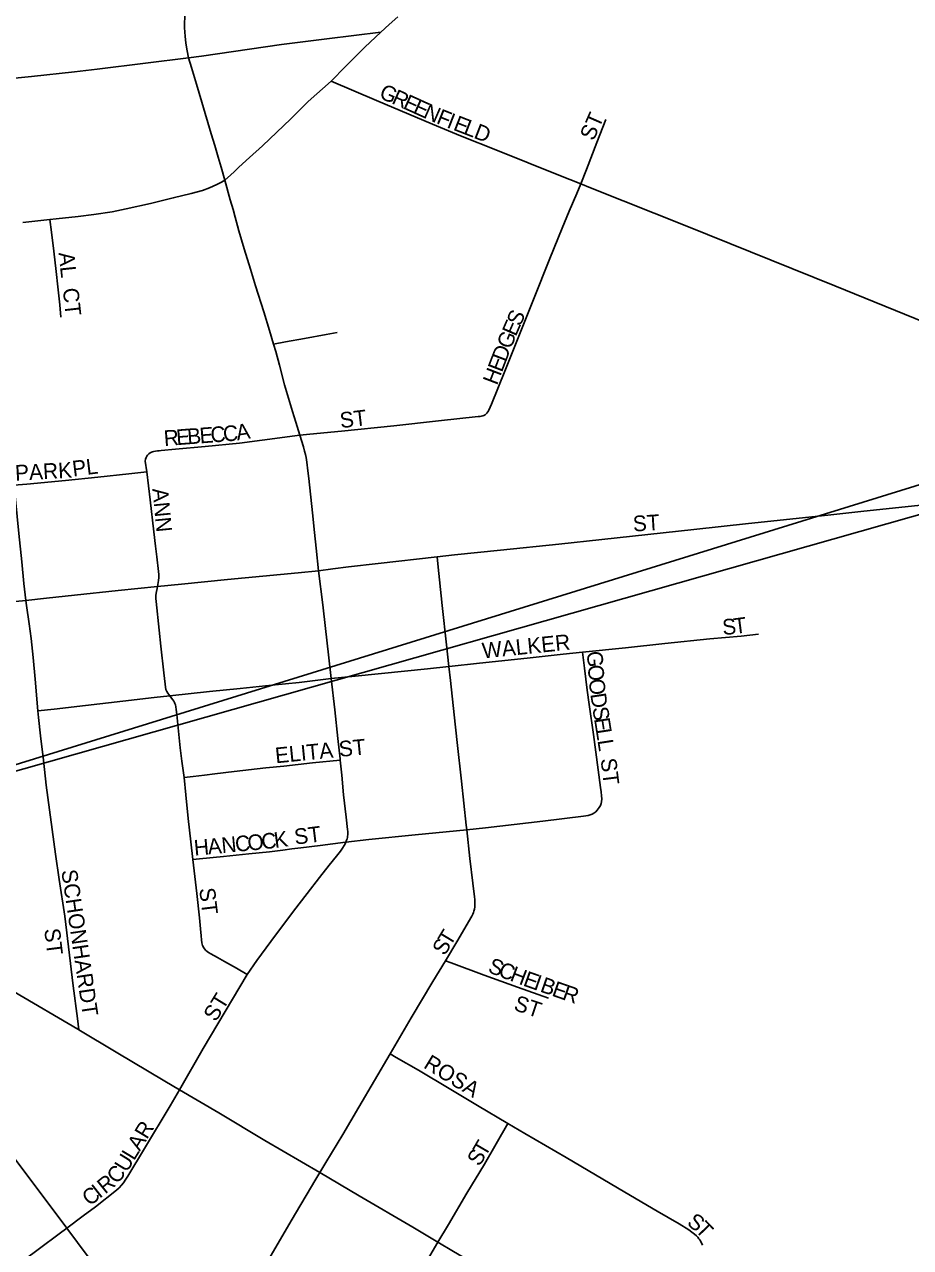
# Model space of a CAD drawing. Extents: x 1772825 to 1773716, y 1138558 to 1139032.
# Drawn here: x 1773356.3 to 1773367.01, y 1138861.97 to 1138876.75 of the extents above; entities that cross this region are included whole.
import ezdxf

# ---------------------------------------------------------------- set-up
doc = ezdxf.new("R2010")
doc.units = 0
for name, color, linetype in [('GM_X_City_Street', 7, 'Continuous'), ('GM_X_City_Street_Text', 7, 'Continuous'), ('GM_X_State_Route', 7, 'Continuous'), ('SH_Text', 7, 'Continuous')]:
    doc.layers.add(name, color=color, linetype=linetype)

msp = doc.modelspace()

# ---------------------------------------------------------------- linework, layer by layer
at = {"layer": 'GM_X_City_Street'}
for points in [[(1773358.286, 1138876.343), (1773358.268, 1138876.429), (1773358.253, 1138876.521), (1773358.243, 1138876.606), (1773358.239, 1138876.653), (1773358.235, 1138876.709), (1773358.236, 1138876.765), (1773358.24, 1138876.829), (1773358.246, 1138876.893), (1773358.254, 1138876.94), (1773358.274, 1138877.016)], [(1773358.725, 1138874.867), (1773358.68, 1138875.024), (1773358.645, 1138875.145), (1773358.604, 1138875.285), (1773358.56, 1138875.427), (1773358.446, 1138875.809), (1773358.381, 1138876.026), (1773358.321, 1138876.225), (1773358.286, 1138876.343)], [(1773360.008, 1138876.063), (1773360.556, 1138875.829), (1773361.234, 1138875.54), (1773361.573, 1138875.403), (1773362.021, 1138875.222), (1773362.761, 1138874.924), (1773363.024, 1138874.82)], [(1773363.024, 1138874.82), (1773363.094, 1138874.996), (1773363.218, 1138875.32), (1773363.327, 1138875.598)], [(1773359.313, 1138872.882), (1773359.264, 1138873.05), (1773359.194, 1138873.276), (1773359.096, 1138873.589), (1773359.035, 1138873.789), (1773358.959, 1138874.036), (1773358.894, 1138874.255), (1773358.877, 1138874.312), (1773358.848, 1138874.417), (1773358.823, 1138874.51), (1773358.79, 1138874.629), (1773358.725, 1138874.867)], [(1773361.853, 1138872.023), (1773361.868, 1138872.031), (1773361.879, 1138872.039), (1773361.885, 1138872.044), (1773361.891, 1138872.05), (1773361.902, 1138872.064), (1773361.909, 1138872.076), (1773361.915, 1138872.087), (1773361.947, 1138872.157), (1773362.107, 1138872.558), (1773362.261, 1138872.938), (1773362.454, 1138873.422), (1773362.651, 1138873.917), (1773362.8, 1138874.286), (1773362.886, 1138874.492), (1773362.976, 1138874.705), (1773363.024, 1138874.82)], [(1773363.024, 1138874.82), (1773363.143, 1138874.774), (1773364.308, 1138874.309), (1773366.096, 1138873.588), (1773367.304, 1138873.099), (1773367.332, 1138873.088)], [(1773356.744, 1138873.209), (1773356.729, 1138873.36), (1773356.705, 1138873.577), (1773356.684, 1138873.763), (1773356.657, 1138874.006), (1773356.631, 1138874.237), (1773356.61, 1138874.392)], [(1773359.313, 1138872.882), (1773359.459, 1138872.911), (1773359.685, 1138872.952), (1773359.948, 1138873), (1773360.082, 1138873.024)], [(1773359.631, 1138871.782), (1773359.63, 1138871.783), (1773359.582, 1138871.942), (1773359.543, 1138872.071), (1773359.482, 1138872.273), (1773359.447, 1138872.391), (1773359.383, 1138872.631), (1773359.339, 1138872.794), (1773359.313, 1138872.882)], [(1773359.631, 1138871.782), (1773359.753, 1138871.796), (1773360.134, 1138871.834), (1773360.766, 1138871.898), (1773361.306, 1138871.956), (1773361.787, 1138872.008), (1773361.806, 1138872.009), (1773361.822, 1138872.012), (1773361.84, 1138872.017), (1773361.853, 1138872.023)], [(1773357.79, 1138871.544), (1773357.804, 1138871.558), (1773357.821, 1138871.569), (1773357.837, 1138871.577), (1773357.851, 1138871.583), (1773357.866, 1138871.587), (1773357.887, 1138871.591), (1773357.909, 1138871.594), (1773357.932, 1138871.596), (1773357.956, 1138871.598), (1773358.128, 1138871.613), (1773358.486, 1138871.645), (1773358.903, 1138871.687), (1773359.174, 1138871.722), (1773359.631, 1138871.782)], [(1773359.857, 1138870.145), (1773359.829, 1138870.418), (1773359.808, 1138870.606), (1773359.784, 1138870.844), (1773359.741, 1138871.259), (1773359.728, 1138871.353), (1773359.714, 1138871.457), (1773359.705, 1138871.512), (1773359.698, 1138871.551), (1773359.688, 1138871.59), (1773359.673, 1138871.644), (1773359.631, 1138871.782)], [(1773357.78, 1138871.339), (1773357.763, 1138871.471), (1773357.765, 1138871.494), (1773357.772, 1138871.516), (1773357.781, 1138871.532), (1773357.79, 1138871.544)], [(1773356.175, 1138871.181), (1773356.332, 1138871.192), (1773356.8, 1138871.236), (1773357.19, 1138871.276), (1773357.566, 1138871.316), (1773357.78, 1138871.339)], [(1773357.912, 1138869.956), (1773357.924, 1138870.027), (1773357.926, 1138870.064), (1773357.925, 1138870.099), (1773357.922, 1138870.137), (1773357.901, 1138870.314), (1773357.886, 1138870.443), (1773357.867, 1138870.614), (1773357.821, 1138871.001), (1773357.78, 1138871.339)], [(1773356.318, 1138869.787), (1773356.297, 1138869.993), (1773356.27, 1138870.255), (1773356.235, 1138870.597), (1773356.193, 1138871.007), (1773356.175, 1138871.181)], [(1773361.288, 1138870.314), (1773361.501, 1138870.338), (1773362.057, 1138870.395), (1773362.759, 1138870.468), (1773363.28, 1138870.524), (1773364.391, 1138870.645), (1773365.051, 1138870.715), (1773365.628, 1138870.775), (1773366.046, 1138870.821), (1773366.444, 1138870.864), (1773367.558, 1138870.982)], [(1773359.857, 1138870.145), (1773360.028, 1138870.168), (1773360.22, 1138870.193), (1773360.579, 1138870.235), (1773361.288, 1138870.314)], [(1773361.431, 1138868.989), (1773361.404, 1138869.249), (1773361.351, 1138869.726), (1773361.296, 1138870.231), (1773361.288, 1138870.314)], [(1773357.912, 1138869.956), (1773358.199, 1138869.984), (1773358.755, 1138870.038), (1773359.61, 1138870.121), (1773359.857, 1138870.145)], [(1773360.01, 1138868.842), (1773359.977, 1138869.128), (1773359.941, 1138869.446), (1773359.907, 1138869.733), (1773359.857, 1138870.145)], [(1773356.318, 1138869.787), (1773356.569, 1138869.815), (1773356.906, 1138869.851), (1773357.436, 1138869.906), (1773357.912, 1138869.956)], [(1773358.058, 1138868.635), (1773358.034, 1138868.666), (1773358.022, 1138868.687), (1773358.013, 1138868.712), (1773358.007, 1138868.738), (1773358.002, 1138868.774), (1773357.986, 1138868.91), (1773357.952, 1138869.233), (1773357.932, 1138869.426), (1773357.894, 1138869.772), (1773357.89, 1138869.81), (1773357.891, 1138869.845), (1773357.895, 1138869.873), (1773357.898, 1138869.895), (1773357.906, 1138869.929), (1773357.912, 1138869.956)], [(1773354.565, 1138869.601), (1773354.871, 1138869.634), (1773355.519, 1138869.699), (1773355.883, 1138869.74), (1773356.108, 1138869.765), (1773356.318, 1138869.787)], [(1773356.465, 1138868.451), (1773356.433, 1138868.837), (1773356.409, 1138869.098), (1773356.385, 1138869.326), (1773356.36, 1138869.503), (1773356.327, 1138869.726), (1773356.318, 1138869.787)], [(1773363.045, 1138869.162), (1773363.564, 1138869.216), (1773364.042, 1138869.268), (1773364.584, 1138869.323), (1773364.964, 1138869.357), (1773365.174, 1138869.378)], [(1773361.431, 1138868.989), (1773361.435, 1138868.989), (1773361.801, 1138869.029), (1773362.377, 1138869.09), (1773362.813, 1138869.137), (1773363.045, 1138869.162)], [(1773363.225, 1138867.252), (1773363.249, 1138867.283), (1773363.263, 1138867.307), (1773363.271, 1138867.331), (1773363.275, 1138867.355), (1773363.278, 1138867.388), (1773363.277, 1138867.425), (1773363.272, 1138867.474), (1773363.265, 1138867.527), (1773363.179, 1138868.166), (1773363.128, 1138868.53), (1773363.104, 1138868.702), (1773363.069, 1138868.968), (1773363.045, 1138869.162)], [(1773360.01, 1138868.842), (1773360.301, 1138868.872), (1773360.895, 1138868.934), (1773361.175, 1138868.962), (1773361.431, 1138868.989)], [(1773361.647, 1138867.016), (1773361.641, 1138867.07), (1773361.585, 1138867.604), (1773361.532, 1138868.07), (1773361.496, 1138868.404), (1773361.45, 1138868.818), (1773361.431, 1138868.989)], [(1773358.058, 1138868.635), (1773358.539, 1138868.685), (1773358.908, 1138868.723), (1773359.294, 1138868.762), (1773359.621, 1138868.795), (1773360.01, 1138868.842)], [(1773360.118, 1138867.858), (1773360.116, 1138867.873), (1773360.09, 1138868.119), (1773360.052, 1138868.465), (1773360.01, 1138868.842)], [(1773356.465, 1138868.451), (1773356.663, 1138868.474), (1773357.04, 1138868.518), (1773357.492, 1138868.57), (1773357.872, 1138868.614), (1773358.058, 1138868.635)], [(1773358.231, 1138867.646), (1773358.205, 1138867.844), (1773358.185, 1138868.004), (1773358.151, 1138868.326), (1773358.143, 1138868.41), (1773358.137, 1138868.469), (1773358.133, 1138868.5), (1773358.127, 1138868.525), (1773358.121, 1138868.541), (1773358.115, 1138868.555), (1773358.108, 1138868.568), (1773358.097, 1138868.584), (1773358.079, 1138868.607), (1773358.058, 1138868.635)], [(1773356.958, 1138864.597), (1773356.942, 1138864.734), (1773356.893, 1138865.131), (1773356.79, 1138865.973), (1773356.723, 1138866.413), (1773356.676, 1138866.722), (1773356.567, 1138867.553), (1773356.531, 1138867.858), (1773356.497, 1138868.152), (1773356.473, 1138868.371), (1773356.465, 1138868.451)], [(1773358.231, 1138867.646), (1773358.341, 1138867.659), (1773358.478, 1138867.676), (1773358.602, 1138867.691), (1773358.837, 1138867.719), (1773359.221, 1138867.762), (1773359.439, 1138867.786), (1773359.782, 1138867.826), (1773360.118, 1138867.858)], [(1773360.186, 1138866.867), (1773360.195, 1138866.889), (1773360.201, 1138866.906), (1773360.206, 1138866.923), (1773360.208, 1138866.939), (1773360.21, 1138866.956), (1773360.211, 1138866.976), (1773360.209, 1138866.995), (1773360.207, 1138867.02), (1773360.192, 1138867.167), (1773360.16, 1138867.439), (1773360.137, 1138867.675), (1773360.118, 1138867.858)], [(1773358.336, 1138866.656), (1773358.313, 1138866.868), (1773358.28, 1138867.153), (1773358.252, 1138867.437), (1773358.231, 1138867.646)], [(1773361.647, 1138867.016), (1773361.875, 1138867.039), (1773362.567, 1138867.12), (1773363.058, 1138867.179), (1773363.114, 1138867.187), (1773363.14, 1138867.194), (1773363.164, 1138867.204), (1773363.185, 1138867.216), (1773363.206, 1138867.232), (1773363.225, 1138867.252)], [(1773360.186, 1138866.867), (1773360.463, 1138866.896), (1773361.024, 1138866.953), (1773361.647, 1138867.016)], [(1773361.391, 1138865.433), (1773361.529, 1138865.661), (1773361.71, 1138865.973), (1773361.721, 1138865.997), (1773361.728, 1138866.014), (1773361.735, 1138866.032), (1773361.741, 1138866.057), (1773361.746, 1138866.084), (1773361.747, 1138866.108), (1773361.747, 1138866.138), (1773361.744, 1138866.174), (1773361.74, 1138866.207), (1773361.719, 1138866.37), (1773361.686, 1138866.669), (1773361.647, 1138867.016)], [(1773358.336, 1138866.656), (1773358.417, 1138866.664), (1773358.709, 1138866.691), (1773359.016, 1138866.724), (1773359.263, 1138866.75), (1773359.423, 1138866.77), (1773359.533, 1138866.784), (1773359.644, 1138866.798), (1773359.878, 1138866.826), (1773360.184, 1138866.867), (1773360.186, 1138866.867)], [(1773358.993, 1138865.268), (1773359.109, 1138865.434), (1773359.279, 1138865.664), (1773359.554, 1138866.03), (1773359.721, 1138866.244), (1773359.87, 1138866.438), (1773359.986, 1138866.587), (1773360.072, 1138866.695), (1773360.12, 1138866.756), (1773360.148, 1138866.795), (1773360.165, 1138866.826), (1773360.177, 1138866.845), (1773360.186, 1138866.867)], [(1773358.993, 1138865.268), (1773358.864, 1138865.344), (1773358.721, 1138865.424), (1773358.634, 1138865.473), (1773358.556, 1138865.517), (1773358.526, 1138865.533), (1773358.509, 1138865.544), (1773358.492, 1138865.56), (1773358.469, 1138865.588), (1773358.455, 1138865.617), (1773358.446, 1138865.648), (1773358.441, 1138865.687), (1773358.437, 1138865.735), (1773358.43, 1138865.817), (1773358.418, 1138865.953), (1773358.387, 1138866.246), (1773358.336, 1138866.656)], [(1773354.992, 1138865.759), (1773355.473, 1138865.477), (1773356.178, 1138865.057), (1773356.947, 1138864.604), (1773356.958, 1138864.597)], [(1773360.72, 1138864.307), (1773360.975, 1138864.741), (1773361.238, 1138865.181), (1773361.391, 1138865.433)], [(1773361.391, 1138865.433), (1773361.458, 1138865.408), (1773361.858, 1138865.258), (1773362.262, 1138865.112), (1773362.636, 1138864.979)], [(1773358.175, 1138863.873), (1773358.464, 1138864.374), (1773358.993, 1138865.268)], [(1773356.958, 1138864.597), (1773357.411, 1138864.328), (1773357.998, 1138863.977), (1773358.175, 1138863.873)], [(1773359.872, 1138862.874), (1773359.944, 1138862.996), (1773360.149, 1138863.335), (1773360.343, 1138863.665), (1773360.72, 1138864.307)], [(1773360.72, 1138864.307), (1773360.796, 1138864.264), (1773361.065, 1138864.11), (1773361.434, 1138863.89), (1773361.778, 1138863.682), (1773362.143, 1138863.465)], [(1773356.814, 1138862.201), (1773357.013, 1138862.349), (1773357.162, 1138862.461), (1773357.416, 1138862.662), (1773357.448, 1138862.69), (1773357.477, 1138862.721), (1773357.5, 1138862.751), (1773357.529, 1138862.793), (1773357.554, 1138862.831), (1773357.753, 1138863.162), (1773358.064, 1138863.681), (1773358.175, 1138863.873)], [(1773358.175, 1138863.873), (1773358.65, 1138863.593), (1773359.209, 1138863.262), (1773359.872, 1138862.874)], [(1773361.299, 1138862.032), (1773361.425, 1138862.247), (1773361.648, 1138862.624), (1773361.86, 1138862.975), (1773362.143, 1138863.465)], [(1773362.143, 1138863.465), (1773362.348, 1138863.344), (1773362.847, 1138863.057), (1773363.559, 1138862.638), (1773363.949, 1138862.405), (1773364.214, 1138862.252), (1773364.331, 1138862.18), (1773364.368, 1138862.154), (1773364.401, 1138862.129), (1773364.423, 1138862.109), (1773364.44, 1138862.092), (1773364.453, 1138862.074), (1773364.464, 1138862.059), (1773364.48, 1138862.032), (1773364.495, 1138861.995)], [(1773358.996, 1138861.464), (1773359.016, 1138861.484), (1773359.059, 1138861.53), (1773359.079, 1138861.556), (1773359.097, 1138861.58), (1773359.13, 1138861.624), (1773359.178, 1138861.698), (1773359.229, 1138861.779), (1773359.524, 1138862.288), (1773359.824, 1138862.792), (1773359.872, 1138862.874)], [(1773359.872, 1138862.874), (1773360.347, 1138862.593), (1773360.997, 1138862.212), (1773361.299, 1138862.032)], [(1773355.459, 1138861.575), (1773355.588, 1138861.589), (1773355.683, 1138861.601), (1773355.774, 1138861.614), (1773355.831, 1138861.623), (1773355.886, 1138861.634), (1773355.936, 1138861.643), (1773355.976, 1138861.651), (1773356.008, 1138861.66), (1773356.037, 1138861.669), (1773356.074, 1138861.681), (1773356.102, 1138861.693), (1773356.123, 1138861.702), (1773356.145, 1138861.714), (1773356.17, 1138861.728), (1773356.198, 1138861.747), (1773356.246, 1138861.779), (1773356.296, 1138861.814), (1773356.485, 1138861.955), (1773356.723, 1138862.134), (1773356.814, 1138862.201)], [(1773360.452, 1138860.592), (1773360.655, 1138860.94), (1773360.928, 1138861.403), (1773361.201, 1138861.867), (1773361.299, 1138862.032)], [(1773361.299, 1138862.032), (1773361.489, 1138861.919), (1773361.948, 1138861.649), (1773362.722, 1138861.194)]]:
    msp.add_lwpolyline(points, dxfattribs=at)
at = {"layer": 'GM_X_State_Route'}
for points in [[(1773360.609, 1138876.652), (1773360.71, 1138876.745), (1773360.816, 1138876.841)], [(1773360.609, 1138876.652), (1773359.957, 1138876.572), (1773359.408, 1138876.505), (1773358.443, 1138876.362), (1773358.286, 1138876.343), (1773357.766, 1138876.278), (1773357.182, 1138876.206), (1773356.908, 1138876.173), (1773356.388, 1138876.119), (1773356.026, 1138876.082)], [(1773360.008, 1138876.063), (1773360.183, 1138876.239), (1773360.414, 1138876.471), (1773360.609, 1138876.652)], [(1773356.282, 1138874.355), (1773356.61, 1138874.392), (1773356.687, 1138874.4), (1773356.95, 1138874.428), (1773357.143, 1138874.45), (1773357.364, 1138874.484), (1773357.533, 1138874.519), (1773357.826, 1138874.584), (1773358.101, 1138874.651), (1773358.316, 1138874.705), (1773358.454, 1138874.742), (1773358.538, 1138874.771), (1773358.628, 1138874.812), (1773358.682, 1138874.84), (1773358.725, 1138874.867), (1773358.793, 1138874.925), (1773358.842, 1138874.971), (1773358.893, 1138875.021), (1773359.022, 1138875.138), (1773359.181, 1138875.282), (1773359.52, 1138875.608), (1773359.732, 1138875.816), (1773360.008, 1138876.063)], [(1773358.016, 1138860.614), (1773357.968, 1138860.678), (1773357.202, 1138861.681), (1773356.814, 1138862.201), (1773356.481, 1138862.648), (1773355.942, 1138863.36), (1773355.699, 1138863.688), (1773355.15, 1138864.422), (1773355.11, 1138864.476), (1773354.35, 1138865.506), (1773353.872, 1138866.139), (1773353.808, 1138866.229), (1773353.668, 1138866.436), (1773353.635, 1138866.486), (1773353.604, 1138866.528), (1773353.579, 1138866.558), (1773353.556, 1138866.583), (1773353.553, 1138866.586), (1773353.484, 1138866.639), (1773353.423, 1138866.684), (1773353.362, 1138866.728), (1773353.293, 1138866.777), (1773353.233, 1138866.818), (1773353.166, 1138866.864)]]:
    msp.add_lwpolyline(points, dxfattribs=at)
at = {"layer": 'SH_Text'}
msp.add_lwpolyline([(1773543.413, 1138925.808), (1773353.166, 1138866.864), (1773543.413, 1138920.862)], close=True, dxfattribs=at)

# ---------------------------------------------------------------- texts
at = {"layer": 'GM_X_City_Street_Text'}
for s, height, rotation, p in [('G', 0.189, 335.7912, (1773360.577, 1138875.865)), ('R', 0.189, 335.7986, (1773360.729, 1138875.797)), ('E', 0.189, 335.7934, (1773360.866, 1138875.736)), ('E', 0.189, 335.7977, (1773360.987, 1138875.681)), ('N', 0.189, 336.4504, (1773361.111, 1138875.625)), ('F', 0.189, 338.3393, (1773361.27, 1138875.556)), ('I', 0.189, 338.6686, (1773361.395, 1138875.506)), ('E', 0.189, 338.6809, (1773361.473, 1138875.476)), ('ST', 0.1894, 66.3692, (1773363.18, 1138875.331)), ('L', 0.189, 338.6604, (1773361.597, 1138875.428)), ('D', 0.189, 338.6733, (1773361.721, 1138875.379)), ('AL', 0.1894, 276.0066, (1773356.715, 1138873.987)), ('CT', 0.1894, 276.3362, (1773356.765, 1138873.554)), ('S', 0.189, 66.0625, (1773362.293, 1138873.09)), ('E', 0.189, 66.4786, (1773362.24, 1138872.968)), ('G', 0.189, 68.3285, (1773362.179, 1138872.814)), ('D', 0.189, 69.058, (1773362.12, 1138872.659)), ('E', 0.189, 69.0507, (1773362.072, 1138872.535)), ('H', 0.189, 69.0551, (1773362.012, 1138872.379)), ('ST', 0.1894, 6.7054, (1773360.125, 1138871.868)), ('A', 0.189, 8.8555, (1773358.874, 1138871.72)), ('R', 0.189, 4.2777, (1773357.993, 1138871.652)), ('E', 0.189, 4.2667, (1773358.143, 1138871.663)), ('B', 0.189, 4.2697, (1773358.276, 1138871.673)), ('E', 0.189, 4.2685, (1773358.425, 1138871.684)), ('C', 0.189, 4.2697, (1773358.558, 1138871.694)), ('C', 0.189, 4.7689, (1773358.71, 1138871.705)), ('PL', 0.1894, 7.1217, (1773356.892, 1138871.283)), ('PARK', 0.1894, 3.1778, (1773356.194, 1138871.233)), ('ANN', 0.1894, 275.5312, (1773357.848, 1138871.136)), ('ST', 0.1894, 3.5746, (1773363.66, 1138870.619)), ('S', 0.189, 4.868, (1773364.743, 1138869.369)), ('T', 0.189, 7.3107, (1773364.885, 1138869.381)), ('WALKER', 0.1894, 5.8034, (1773361.842, 1138869.085)), ('G', 0.189, 274.1339, (1773363.098, 1138869.169)), ('O', 0.189, 274.1576, (1773363.11, 1138869.003)), ('O', 0.189, 275.4704, (1773363.122, 1138868.832)), ('D', 0.189, 278.5243, (1773363.14, 1138868.655)), ('S', 0.189, 278.8276, (1773363.165, 1138868.489)), ('E', 0.189, 278.841, (1773363.185, 1138868.357)), ('L', 0.189, 278.8334, (1773363.206, 1138868.225)), ('ELITA ST', 0.1894, 5.7131, (1773359.341, 1138867.818)), ('L', 0.189, 278.841, (1773363.226, 1138868.094)), ('ST', 0.1894, 277.1351, (1773363.264, 1138867.871)), ('ST', 0.1894, 7.1217, (1773359.575, 1138866.835)), ('H', 0.189, 5.2973, (1773358.359, 1138866.702)), ('A', 0.189, 5.3237, (1773358.525, 1138866.717)), ('N', 0.189, 5.2973, (1773358.691, 1138866.733)), ('C', 0.189, 5.3281, (1773358.857, 1138866.748)), ('O', 0.189, 5.2973, (1773359.006, 1138866.762)), ('C', 0.189, 6.2933, (1773359.176, 1138866.778)), ('K', 0.189, 7.5526, (1773359.33, 1138866.795)), ('SCHONHARDT', 0.1894, 278.3827, (1773356.748, 1138866.522)), ('ST', 0.1894, 277.1351, (1773358.414, 1138866.304)), ('ST', 0.1894, 277.1217, (1773356.541, 1138865.814)), ('T', 0.189, 58.8113, (1773361.449, 1138865.599)), ('S', 0.189, 59.5705, (1773361.382, 1138865.484)), ('S', 0.189, 338.6604, (1773361.892, 1138865.299)), ('C', 0.189, 338.654, (1773362.016, 1138865.251)), ('H', 0.189, 339.2715, (1773362.158, 1138865.196)), ('E', 0.189, 340.5065, (1773362.318, 1138865.135)), ('I', 0.189, 340.7201, (1773362.445, 1138865.09)), ('B', 0.189, 340.6974, (1773362.523, 1138865.063)), ('E', 0.189, 340.7302, (1773362.665, 1138865.013)), ('R', 0.189, 340.7203, (1773362.791, 1138864.969)), ('ST', 0.1894, 58.3953, (1773358.615, 1138864.685)), ('ST', 0.1894, 341.5607, (1773362.204, 1138864.841)), ('ROSA', 0.1894, 328.4929, (1773361.114, 1138864.147)), ('R', 0.189, 58.803, (1773357.783, 1138863.266)), ('A', 0.189, 58.8169, (1773357.696, 1138863.123)), ('T', 0.189, 59.5818, (1773361.872, 1138863.055)), ('U', 0.189, 58.3728, (1773357.539, 1138862.866)), ('L', 0.189, 58.7903, (1773357.627, 1138863.009)), ('S', 0.189, 58.4319, (1773361.8, 1138862.938)), ('C', 0.189, 48.498, (1773357.419, 1138862.725)), ('R', 0.189, 38.8917, (1773357.277, 1138862.607)), ('C', 0.189, 38.0454, (1773357.091, 1138862.461)), ('I', 0.189, 38.0483, (1773357.209, 1138862.554)), ('S', 0.189, 323.7858, (1773364.297, 1138862.247)), ('T', 0.189, 313.6669, (1773364.398, 1138862.174))]:
    msp.add_text(s, height=height, rotation=rotation, dxfattribs=at).set_placement(p)

doc.saveas('drawing.dxf')
